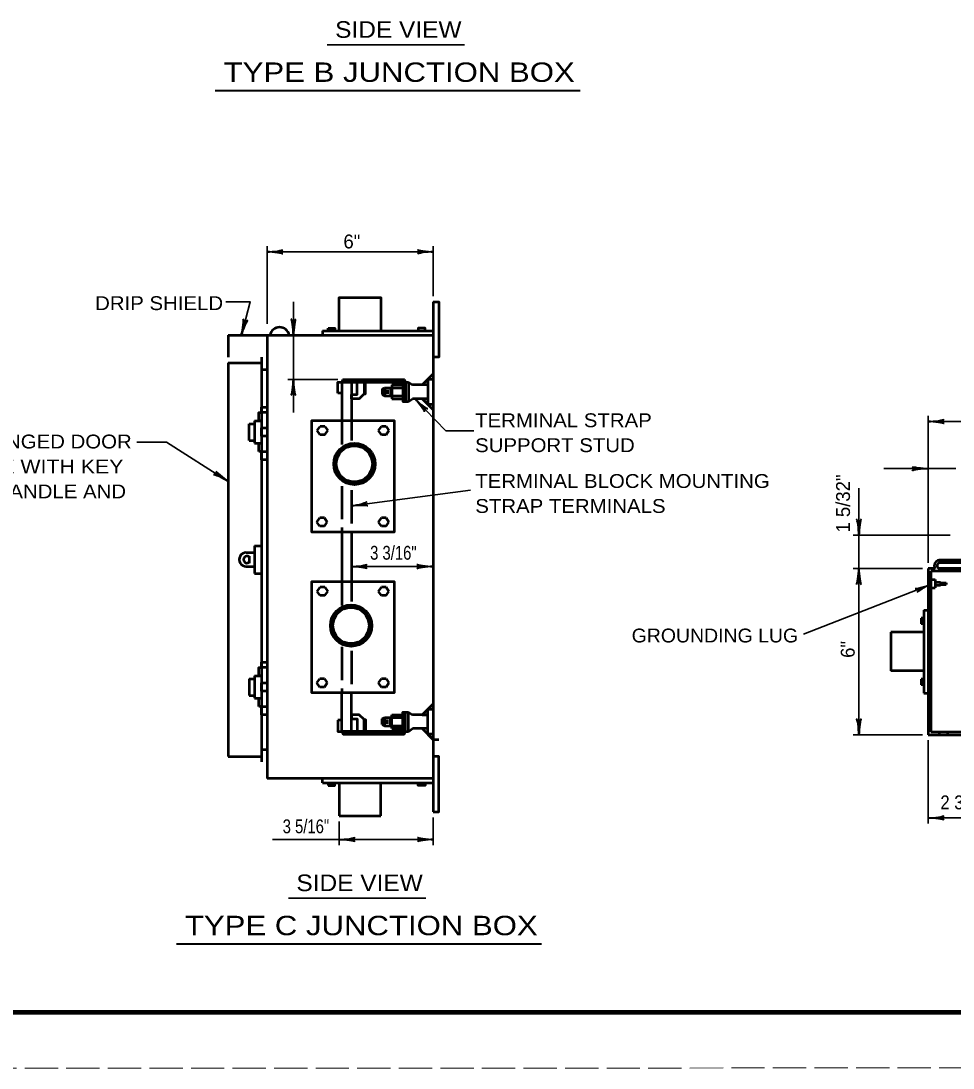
# Model space of a CAD drawing. Extents: x -1 to 679, y 0 to 440.
# Drawn here: x 229.6 to 397.8, y 0.4 to 189.2 of the extents above; entities that cross this region are included whole.
import ezdxf

# ---------------------------------------------------------------- set-up
doc = ezdxf.new("R2010")
doc.units = 0
doc.linetypes.add('LONG_DASHED', pattern=[7.5, 6, -1.5])
doc.layers.add('1', color=7, linetype='Continuous', lineweight=53)
doc.layers.add('61', color=7, linetype='Continuous', lineweight=35)

msp = doc.modelspace()

# ---------------------------------------------------------------- linework, layer by layer
at = {"layer": '1', "lineweight": 35}
for p, q in [((284.847, 184.891), (309.613, 184.891)), ((273.981, 134.577), (273.981, 148.577)), ((273.981, 147.577), (303.981, 147.577)), ((303.981, 139.577), (303.981, 148.577)), ((286.731, 124.577), (277.731, 124.577)), ((278.731, 124.577), (278.731, 118.577)), ((393.265, 91.475), (393.265, 117.975)), ((393.265, 116.975), (453.765, 116.975)), ((393.265, 108.475), (385.265, 108.475)), ((398.265, 108.475), (393.265, 108.475)), ((289.26, 101.764), (310.675, 104.575)), ((380.765, 96.475), (380.765, 104.975)), ((397.265, 96.475), (379.765, 96.475)), ((289.158, 90.818), (303.908, 90.818)), ((392.265, 90.475), (379.765, 90.475)), ((393.754, 87.555), (370.778, 78.594)), ((392.265, 60.475), (379.765, 60.475)), ((393.265, 59.475), (393.265, 44.475)), ((303.981, 45.577), (303.981, 40.577)), ((393.265, 45.475), (405.39, 45.475)), ((286.981, 44.827), (286.981, 40.577)), ((286.981, 41.577), (274.981, 41.577)), ((286.981, 41.577), (303.981, 41.577)), ((277.854, 30.978), (302.621, 30.978))]:
    msp.add_line(p, q, dxfattribs=at)
at = {"layer": '1', "lineweight": 40}
for p, q in [((264.611, 176.668), (330.479, 176.668)), ((257.619, 22.756), (323.487, 22.756))]:
    msp.add_line(p, q, dxfattribs=at)
at = {"layer": '1'}
for p, q in [((303.981, 138.577), (303.981, 124.577)), ((266.981, 132.577), (273.981, 132.577)), ((266.981, 132.577), (266.981, 128.577)), ((273.981, 132.577), (273.981, 52.577)), ((274.481, 132.577), (277.981, 132.577)), ((283.981, 133.327), (303.981, 133.327)), ((283.981, 133.327), (283.981, 132.577)), ((284.981, 133.327), (284.981, 133.827)), ((272.981, 128.577), (272.981, 117.077)), ((266.981, 127.577), (272.981, 127.577)), ((266.981, 127.577), (266.981, 56.577)), ((272.981, 126.327), (273.981, 126.327)), ((301.981, 123.577), (303.981, 125.577)), ((287.481, 124.077), (290.231, 124.077)), ((287.481, 124.077), (287.481, 117.077)), ((291.34, 124.077), (298.981, 124.077)), ((294.731, 122.827), (295.231, 123.077)), ((294.731, 122.827), (294.731, 121.827)), ((295.231, 123.077), (298.481, 123.077)), ((295.231, 123.077), (295.231, 121.577)), ((296.231, 123.077), (296.231, 121.577)), ((296.481, 123.577), (298.481, 123.577)), ((296.481, 123.577), (296.481, 121.077)), ((298.481, 124.077), (298.671, 124.077)), ((298.981, 124.077), (298.981, 120.577)), ((298.981, 124.077), (299.481, 124.077)), ((299.481, 124.077), (299.481, 120.577)), ((299.481, 124.077), (300.231, 123.577)), ((302.981, 123.577), (300.231, 123.577)), ((302.981, 124.577), (302.981, 120.077)), ((303.981, 124.577), (303.981, 119.077)), ((289.231, 121.077), (289.231, 117.077)), ((294.731, 121.827), (295.231, 121.577)), ((295.231, 121.577), (298.481, 121.577)), ((295.731, 122.702), (295.731, 121.952)), ((296.481, 121.077), (298.481, 121.077)), ((299.481, 120.577), (300.231, 121.077)), ((302.981, 121.077), (300.231, 121.077)), ((301.981, 121.077), (303.981, 119.077)), ((303.981, 119.077), (303.981, 46.577)), ((273.981, 118.577), (273.981, 114.327)), ((270.731, 116.577), (271.731, 116.577)), ((270.731, 113.577), (270.731, 116.577)), ((271.731, 117.077), (271.731, 113.077)), ((271.731, 117.077), (272.981, 117.077)), ((272.981, 117.077), (272.981, 114.327)), ((283.044, 115.327), (283.544, 116.077)), ((283.544, 114.577), (283.044, 115.327)), ((284.419, 116.077), (283.544, 116.077)), ((284.419, 116.077), (284.919, 115.327)), ((284.419, 114.577), (284.919, 115.327)), ((294.106, 115.327), (294.606, 116.077)), ((294.606, 114.577), (294.106, 115.327)), ((295.481, 116.077), (294.606, 116.077)), ((295.481, 116.077), (295.981, 115.327)), ((295.481, 114.577), (295.981, 115.327)), ((270.731, 113.577), (271.731, 113.577)), ((272.981, 114.327), (272.981, 113.077)), ((273.981, 114.327), (273.981, 110.077)), ((284.419, 114.577), (283.544, 114.577)), ((295.481, 114.577), (294.606, 114.577)), ((271.731, 113.077), (272.981, 113.077)), ((282.981, 98.827), (283.481, 99.577)), ((283.481, 98.077), (282.981, 98.827)), ((284.356, 99.577), (283.481, 99.577)), ((284.356, 99.577), (284.856, 98.827)), ((284.356, 98.077), (284.856, 98.827)), ((294.106, 98.827), (294.606, 99.577)), ((294.606, 98.077), (294.106, 98.827)), ((295.481, 99.577), (294.606, 99.577)), ((295.481, 99.577), (295.981, 98.827)), ((295.481, 98.077), (295.981, 98.827)), ((284.356, 98.077), (283.481, 98.077)), ((287.481, 97.077), (287.481, 88.077)), ((289.231, 97.077), (289.231, 88.077)), ((295.481, 98.077), (294.606, 98.077)), ((271.731, 94.577), (271.731, 89.577)), ((271.731, 94.577), (272.981, 94.577)), ((270.231, 93.327), (271.731, 93.327)), ((270.731, 92.702), (270.731, 91.452)), ((270.231, 90.827), (271.731, 90.827)), ((399.265, 91.975), (395.265, 91.975)), ((399.265, 91.475), (395.265, 91.475)), ((271.731, 89.577), (272.981, 89.577)), ((394.515, 90.475), (393.265, 90.475)), ((393.265, 90.475), (393.265, 60.475)), ((393.765, 88.975), (393.265, 88.975)), ((401.515, 89.975), (393.765, 89.975)), ((393.765, 89.975), (393.765, 60.975)), ((401.015, 90.475), (395.265, 90.475)), ((395.515, 90.475), (395.515, 89.975)), ((397.015, 90.475), (397.015, 89.975)), ((283.044, 86.327), (283.544, 87.077)), ((284.419, 87.077), (283.544, 87.077)), ((284.419, 87.077), (284.919, 86.327)), ((294.106, 86.327), (294.606, 87.077)), ((295.481, 87.077), (294.606, 87.077)), ((295.481, 87.077), (295.981, 86.327)), ((393.765, 87.475), (393.265, 87.475)), ((393.765, 88.475), (394.515, 88.475)), ((393.765, 86.975), (394.515, 86.975)), ((394.515, 88.475), (394.515, 86.975)), ((394.515, 87.975), (395.515, 87.975)), ((394.515, 87.475), (395.515, 87.475)), ((395.515, 87.975), (395.515, 87.475)), ((395.515, 87.85), (396.515, 87.85)), ((395.515, 87.6), (396.515, 87.6)), ((396.515, 87.85), (396.515, 87.6)), ((283.544, 85.577), (283.044, 86.327)), ((284.419, 85.577), (283.544, 85.577)), ((284.419, 85.577), (284.919, 86.327)), ((294.606, 85.577), (294.106, 86.327)), ((295.481, 85.577), (294.606, 85.577)), ((295.481, 85.577), (295.981, 86.327)), ((393.765, 85.975), (393.265, 85.975)), ((393.765, 84.475), (393.265, 84.475)), ((392.515, 81.475), (392.015, 81.475)), ((392.015, 81.475), (392.015, 80.475)), ((392.515, 82.975), (392.515, 67.975)), ((392.515, 82.975), (393.265, 82.975)), ((393.765, 82.975), (393.265, 82.975)), ((393.765, 81.475), (393.265, 81.475)), ((392.515, 80.475), (392.015, 80.475)), ((393.765, 79.975), (393.265, 79.975)), ((392.515, 78.975), (386.515, 78.975)), ((386.515, 78.975), (386.515, 71.975)), ((393.765, 78.475), (393.265, 78.475)), ((393.765, 76.975), (393.265, 76.975)), ((393.765, 75.475), (393.265, 75.475)), ((393.765, 73.975), (393.265, 73.975)), ((273.981, 72.577), (273.981, 68.327)), ((392.515, 71.975), (386.515, 71.975)), ((393.765, 72.475), (393.265, 72.475)), ((270.731, 70.577), (271.731, 70.577)), ((270.731, 70.577), (270.731, 67.577)), ((271.731, 71.077), (271.731, 67.077)), ((271.731, 71.077), (272.981, 71.077)), ((272.981, 71.077), (272.981, 68.327)), ((282.981, 69.827), (283.481, 70.577)), ((284.356, 70.577), (283.481, 70.577)), ((284.356, 70.577), (284.856, 69.827)), ((294.106, 69.827), (294.606, 70.577)), ((295.481, 70.577), (294.606, 70.577)), ((295.481, 70.577), (295.981, 69.827)), ((392.515, 70.475), (392.015, 70.475)), ((392.015, 70.475), (392.015, 69.475)), ((393.765, 70.975), (393.265, 70.975)), ((273.981, 68.327), (273.981, 64.077)), ((283.481, 69.077), (282.981, 69.827)), ((284.356, 69.077), (283.481, 69.077)), ((284.356, 69.077), (284.856, 69.827)), ((287.481, 61.077), (287.481, 68.077)), ((289.231, 64.077), (289.231, 68.077)), ((294.606, 69.077), (294.106, 69.827)), ((295.481, 69.077), (294.606, 69.077)), ((295.481, 69.077), (295.981, 69.827)), ((392.515, 69.475), (392.015, 69.475)), ((393.765, 69.475), (393.265, 69.475)), ((270.731, 67.577), (271.731, 67.577)), ((271.731, 67.077), (272.981, 67.077)), ((392.515, 67.975), (393.265, 67.975)), ((393.765, 67.975), (393.265, 67.975)), ((393.765, 66.475), (393.265, 66.475)), ((298.981, 61.077), (298.981, 64.577)), ((299.481, 61.077), (299.481, 64.577)), ((299.481, 64.577), (300.231, 64.077)), ((301.981, 64.077), (303.981, 66.077)), ((393.765, 64.975), (393.265, 64.975)), ((294.731, 63.327), (295.231, 63.577)), ((294.731, 62.327), (294.731, 63.327)), ((294.731, 62.327), (295.231, 62.077)), ((295.231, 63.577), (298.481, 63.577)), ((295.231, 62.077), (295.231, 63.577)), ((295.731, 62.452), (295.731, 63.202)), ((296.231, 62.077), (296.231, 63.577)), ((296.481, 64.077), (298.481, 64.077)), ((296.481, 61.577), (296.481, 64.077)), ((302.981, 64.077), (300.231, 64.077)), ((393.765, 63.475), (393.265, 63.475)), ((287.481, 61.077), (290.231, 61.077)), ((291.34, 61.077), (298.981, 61.077)), ((295.231, 62.077), (298.481, 62.077)), ((296.481, 61.577), (298.481, 61.577)), ((298.481, 61.077), (298.671, 61.077)), ((298.981, 61.077), (299.481, 61.077)), ((299.481, 61.077), (300.231, 61.577)), ((302.981, 61.577), (300.231, 61.577)), ((301.981, 61.577), (303.981, 59.577)), ((393.765, 61.975), (393.265, 61.975)), ((395.265, 60.975), (395.265, 60.475)), ((396.765, 60.975), (396.765, 60.475)), ((304.981, 59.577), (303.981, 59.577)), ((272.981, 57.827), (273.981, 57.827)), ((266.981, 56.577), (272.981, 56.577)), ((303.981, 52.577), (273.981, 52.577)), ((283.981, 51.827), (283.981, 52.577)), ((283.981, 51.827), (303.981, 51.827)), ((284.981, 51.827), (284.981, 51.327)), ((286.981, 51.827), (286.981, 45.827)), ((294.481, 45.827), (294.481, 51.827)), ((286.981, 45.827), (294.481, 45.827))]:
    msp.add_line(p, q, dxfattribs=at)
at = {"layer": '1', "linetype": 'LONG_DASHED'}
for p, q in [((287.481, 117.077), (287.481, 112.802)), ((289.231, 117.077), (289.231, 113.532)), ((287.481, 105.333), (287.481, 97.077)), ((289.231, 104.604), (289.231, 97.077)), ((287.481, 88.077), (287.481, 83.802)), ((289.231, 88.077), (289.231, 84.532)), ((287.481, 76.333), (287.481, 68.077)), ((289.231, 75.604), (289.231, 68.077))]:
    msp.add_line(p, q, dxfattribs=at)
at = {"layer": '1', "lineweight": 35}
for points in [[(269.342, 132.577), (270.95, 138.536), (266.529, 138.536)], [(278.731, 124.577), (278.731, 132.577), (278.731, 138.577)], [(300.658, 121.077), (306.234, 115.303), (311.313, 115.303)], [(266.981, 106.149), (255.852, 113.234), (250.466, 113.234)], [(380.765, 96.475), (380.765, 90.475), (380.765, 60.475)]]:
    msp.add_lwpolyline(points, dxfattribs=at)
at = {"layer": '1'}
for points in [[(286.981, 133.327), (286.981, 139.327), (294.481, 139.327), (294.481, 133.327)], [(303.981, 138.577), (304.981, 138.577), (304.981, 128.577), (303.981, 128.577)], [(273.981, 132.577), (277.981, 132.577), (303.981, 132.577)], [(284.981, 133.827), (286.231, 133.827), (286.231, 133.327)], [(302.481, 133.327), (302.481, 133.827), (301.231, 133.827), (301.231, 133.327)], [(289.231, 124.077), (289.231, 121.077), (289.231, 121.827), (290.231, 121.827), (290.231, 124.077), (291.481, 124.077), (291.481, 121.952), (290.606, 121.077), (289.231, 121.077)], [(291.481, 121.952), (291.731, 121.952), (291.731, 124.077)], [(298.481, 124.077), (298.481, 120.577), (299.481, 120.577)], [(272.981, 113.077), (272.981, 71.077), (272.481, 71.077), (272.481, 72.577), (272.981, 72.577), (272.981, 71.077)], [(272.981, 68.327), (272.981, 67.077), (272.981, 55.577)], [(298.481, 61.077), (298.481, 64.577), (299.481, 64.577)], [(302.981, 60.577), (302.981, 65.077), (301.981, 64.077), (302.981, 64.077), (302.981, 65.077)], [(289.231, 61.077), (289.231, 64.077), (289.231, 63.327), (290.231, 63.327), (290.231, 61.077), (291.481, 61.077), (291.481, 63.202), (290.606, 64.077), (289.231, 64.077)], [(291.481, 63.202), (291.731, 63.202), (291.731, 61.077)], [(393.265, 60.475), (408.015, 60.475), (435.515, 60.475)], [(393.765, 60.975), (403.265, 60.975), (407.015, 60.975)], [(303.981, 46.577), (304.981, 46.577), (304.981, 56.577), (303.981, 56.577)], [(284.981, 51.327), (286.231, 51.327), (286.231, 51.827)], [(302.481, 51.827), (302.481, 51.327), (301.231, 51.327), (301.231, 51.827)]]:
    msp.add_lwpolyline(points, dxfattribs=at)
for points in [[(303.981, 124.577), (302.981, 124.577), (303.981, 125.577)], [(286.731, 122.077), (286.731, 124.077), (287.481, 124.077), (287.481, 122.077)], [(287.481, 124.077), (287.731, 124.577), (298.731, 124.577), (298.981, 124.077)], [(302.981, 123.577), (301.981, 123.577), (302.981, 124.577)], [(302.981, 120.077), (301.981, 121.077), (302.981, 121.077)], [(272.981, 118.577), (272.981, 119.577), (273.981, 119.577), (273.981, 118.577)], [(303.981, 119.077), (302.981, 120.077), (303.981, 120.077)], [(272.481, 117.077), (272.481, 118.577), (272.981, 118.577), (272.981, 117.077)], [(272.981, 115.827), (273.981, 115.827), (273.981, 114.327), (272.981, 114.327)], [(287.481, 117.077), (281.981, 117.077), (281.981, 97.077), (296.981, 97.077), (296.981, 117.077)], [(272.481, 111.577), (272.481, 113.077), (272.981, 113.077), (272.981, 111.577)], [(272.981, 111.577), (273.981, 111.577), (273.981, 110.077), (272.981, 110.077)], [(287.481, 88.077), (281.981, 88.077), (281.981, 68.077), (296.981, 68.077), (296.981, 88.077)], [(272.981, 72.577), (272.981, 73.577), (273.981, 73.577), (273.981, 72.577)], [(272.981, 68.327), (272.981, 69.827), (273.981, 69.827), (273.981, 68.327)], [(272.481, 65.577), (272.481, 67.077), (272.981, 67.077), (272.981, 65.577)], [(272.981, 65.577), (273.981, 65.577), (273.981, 64.077), (272.981, 64.077)], [(303.981, 66.077), (302.981, 65.077), (303.981, 65.077)], [(286.731, 63.077), (286.731, 61.077), (287.481, 61.077), (287.481, 63.077)], [(287.481, 61.077), (287.731, 60.577), (298.731, 60.577), (298.981, 61.077)], [(302.981, 61.577), (301.981, 61.577), (302.981, 60.577)], [(303.981, 60.577), (302.981, 60.577), (303.981, 59.577)]]:
    msp.add_lwpolyline(points, close=True, dxfattribs=at)
for centre, radius in [((289.752, 109.318), 3.75), ((289.729, 109.331), 3.5), ((289.729, 109.331), 3.25), ((289.152, 80.158), 3.75), ((289.129, 80.171), 3.5), ((289.129, 80.171), 3.25)]:
    msp.add_circle(centre, radius, dxfattribs=at)
for centre, radius, start, end in [((276.231, 132.168), 1.797, 13.17748, 166.82252), ((270.208, 92.077), 1.25, 88.95104, 271.04896), ((270.351, 92.077), 0.628, 52.75436, 307.24564), ((395.375, 90.983), 0.998, 96.30976, 210.56014), ((395.417, 90.975), 0.523, 106.92536, 253.07464)]:
    msp.add_arc(centre, radius, start, end, dxfattribs=at)
at = {"layer": '1', "lineweight": 40}
for centre, major_axis, ratio, start_param, end_param in [((275.072, 147.854), (-1.786, -0.156), 0.122415, 0.8963533, 3.1415927), ((275.072, 147.854), (-1.786, -0.156), 0.122415, 0.8963533, 3.1415927), ((275.102, 147.366), (-1.756, 0.176), 0.07063, 3.1407148, 5.41811), ((275.102, 147.366), (-1.756, 0.176), 0.07063, 3.1407148, 5.41811), ((302.89, 147.301), (1.786, 0.156), 0.122415, 0.8963533, 3.1415927), ((302.89, 147.301), (1.786, 0.156), 0.122415, 0.8963533, 3.1415927), ((302.861, 147.789), (1.756, -0.176), 0.07063, 3.1407148, 5.41811), ((302.861, 147.789), (1.756, -0.176), 0.07063, 3.1407148, 5.41811), ((269.36, 133.703), (-0.314, -1.765), 0.122415, 0.8963533, 3.1415927), ((269.36, 133.703), (-0.314, -1.765), 0.122415, 0.8963533, 3.1415927), ((269.839, 133.604), (0.627, 1.65), 0.07063, 6.2823074, 8.5597026), ((269.839, 133.604), (0.627, 1.65), 0.07063, 6.2823074, 8.5597026), ((278.455, 133.668), (0.156, -1.786), 0.122415, 0.8963533, 3.1415927), ((278.455, 133.668), (0.156, -1.786), 0.122415, 0.8963533, 3.1415927), ((278.943, 133.698), (-0.176, -1.756), 0.07063, 3.1407148, 5.41811), ((278.943, 133.698), (-0.176, -1.756), 0.07063, 3.1407148, 5.41811), ((278.52, 123.457), (0.176, 1.756), 0.07063, 3.1407148, 5.41811), ((278.52, 123.457), (0.176, 1.756), 0.07063, 3.1407148, 5.41811), ((279.007, 123.486), (-0.156, 1.786), 0.122415, 0.8963533, 3.1415927), ((279.007, 123.486), (-0.156, 1.786), 0.122415, 0.8963533, 3.1415927), ((301.284, 120.124), (1.094, -1.386), 0.07063, 6.2823074, 8.5597026), ((301.284, 120.124), (1.094, -1.386), 0.07063, 6.2823074, 8.5597026), ((301.615, 120.484), (-1.353, 1.176), 0.122415, 0.8963533, 3.1415927), ((301.615, 120.484), (-1.353, 1.176), 0.122415, 0.8963533, 3.1415927), ((394.356, 117.251), (-1.786, -0.156), 0.122415, 0.8963533, 3.1415927), ((394.356, 117.251), (-1.786, -0.156), 0.122415, 0.8963533, 3.1415927), ((394.386, 116.764), (-1.756, 0.176), 0.07063, 3.1407148, 5.41811), ((394.386, 116.764), (-1.756, 0.176), 0.07063, 3.1407148, 5.41811), ((266.15, 106.93), (-1.387, 1.091), 0.07063, 6.2823074, 8.5597026), ((266.15, 106.93), (-1.387, 1.091), 0.07063, 6.2823074, 8.5597026), ((392.174, 108.199), (1.786, 0.156), 0.122415, 0.8963533, 3.1415927), ((392.174, 108.199), (1.786, 0.156), 0.122415, 0.8963533, 3.1415927), ((392.145, 108.687), (1.756, -0.176), 0.07063, 3.1407148, 5.41811), ((392.145, 108.687), (1.756, -0.176), 0.07063, 3.1407148, 5.41811), ((265.912, 106.502), (1.59, -0.827), 0.122415, 0.8963533, 3.1415927), ((265.912, 106.502), (1.59, -0.827), 0.122415, 0.8963533, 3.1415927), ((290.306, 102.18), (-1.75, -0.387), 0.122415, 0.8963533, 3.1415927), ((290.306, 102.18), (-1.75, -0.387), 0.122415, 0.8963533, 3.1415927), ((290.399, 101.701), (1.764, 0.054), 0.07063, 6.2823074, 8.5597026), ((290.399, 101.701), (1.764, 0.054), 0.07063, 6.2823074, 8.5597026), ((380.489, 97.566), (0.156, -1.786), 0.122415, 0.8963533, 3.1415927), ((380.489, 97.566), (0.156, -1.786), 0.122415, 0.8963533, 3.1415927), ((380.977, 97.596), (-0.176, -1.756), 0.07063, 3.1407148, 5.41811), ((380.977, 97.596), (-0.176, -1.756), 0.07063, 3.1407148, 5.41811), ((290.278, 90.607), (-1.756, 0.176), 0.07063, 3.1407148, 5.41811), ((290.278, 90.607), (-1.756, 0.176), 0.07063, 3.1407148, 5.41811), ((290.249, 91.095), (-1.786, -0.156), 0.122415, 0.8963533, 3.1415927), ((290.249, 91.095), (-1.786, -0.156), 0.122415, 0.8963533, 3.1415927), ((302.817, 90.542), (1.786, 0.156), 0.122415, 0.8963533, 3.1415927), ((302.817, 90.542), (1.786, 0.156), 0.122415, 0.8963533, 3.1415927), ((302.787, 91.03), (1.756, -0.176), 0.07063, 3.1407148, 5.41811), ((302.787, 91.03), (1.756, -0.176), 0.07063, 3.1407148, 5.41811), ((380.554, 89.355), (0.176, 1.756), 0.07063, 3.1407148, 5.41811), ((381.041, 89.384), (-0.156, 1.786), 0.122415, 0.8963533, 3.1415927), ((392.633, 87.345), (-1.7, -0.475), 0.07063, 6.2823074, 8.5597026), ((392.633, 87.345), (-1.7, -0.475), 0.07063, 6.2823074, 8.5597026), ((392.838, 86.901), (1.607, 0.794), 0.122415, 0.8963533, 3.1415927), ((392.838, 86.901), (1.607, 0.794), 0.122415, 0.8963533, 3.1415927), ((380.489, 61.566), (0.156, -1.786), 0.122415, 0.8963533, 3.1415927), ((380.977, 61.596), (-0.176, -1.756), 0.07063, 3.1407148, 5.41811), ((394.356, 45.751), (-1.786, -0.156), 0.122415, 0.8963533, 3.1415927), ((394.356, 45.751), (-1.786, -0.156), 0.122415, 0.8963533, 3.1415927), ((394.386, 45.264), (-1.756, 0.176), 0.07063, 3.1407148, 5.41811), ((394.386, 45.264), (-1.756, 0.176), 0.07063, 3.1407148, 5.41811), ((288.072, 41.854), (-1.786, -0.156), 0.122415, 0.8963533, 3.1415927), ((288.102, 41.366), (-1.756, 0.176), 0.07063, 3.1407148, 5.41811), ((302.89, 41.301), (1.786, 0.156), 0.122415, 0.8963533, 3.1415927), ((302.861, 41.789), (1.756, -0.176), 0.07063, 3.1407148, 5.41811)]:
    msp.add_ellipse(centre, major_axis=major_axis, ratio=ratio, start_param=start_param, end_param=end_param, dxfattribs=at)
at = {"layer": '61', "lineweight": 158}
msp.add_line((667.823, 10.358), (28.763, 10.378), dxfattribs=at)
at = {"layer": '61', "linetype": 'LONG_DASHED', "lineweight": 13}
msp.add_line((678.763, 0.378), (-1.297, 0.358), dxfattribs=at)

# ---------------------------------------------------------------- texts
at = {"layer": '1'}
for s, height, width, p in [('SIDE VIEW', 3, 1.1, (286.267, 186.18)), ('TYPE B JUNCTION BOX', 3.5, 1.2, (266.146, 178.234)), ('DRIP SHIELD', 2.5, 1.1, (242.962, 137.07)), ('TERMINAL STRAP', 2.5, 1.1, (311.522, 115.95)), ('GASKET HINGED DOOR', 2.5, 1.1, (207.266, 112.113)), ('SUPPORT STUD', 2.5, 1.1, (311.522, 111.45)), ('COMPLETE WITH KEY', 2.5, 1.15, (207.266, 107.613)), ('TERMINAL BLOCK MOUNTING', 2.5, 1.1, (311.556, 104.989)), ('LOCKING HANDLE AND', 2.5, 1.1, (207.266, 103.113)), ('STRAP TERMINALS', 2.5, 1.1, (311.556, 100.489)), ('3 3/16"', 2.5, 0.8, (292.579, 92.048)), ('GROUNDING LUG', 2.5, 1.05, (339.768, 77.122)), ('2 3/8"', 2.5, 0.9, (395.473, 47.024)), ('3 5/16"', 2.5, 0.8, (276.801, 42.708)), ('SIDE VIEW', 3, 1.1, (279.275, 32.268)), ('TYPE C JUNCTION BOX', 3.5, 1.2, (259.153, 24.321))]:
    msp.add_text(s, height=height, dxfattribs=dict(at, width=width)).set_placement(p)
msp.add_text('6"', height=2.5, dxfattribs=at).set_placement((287.76, 148.197))
for s, p in [('1 5/32"', (379.161, 96.945)), ('6"', (380.006, 74.342))]:
    msp.add_text(s, height=2.5, rotation=90, dxfattribs=at).set_placement(p)

doc.saveas('drawing.dxf')
